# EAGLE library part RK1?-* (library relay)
1.5 GHz MICROWAVE RELAY NAiS Source: http://www.mew-europe.com/.. en_ds_61311_0000.pdf
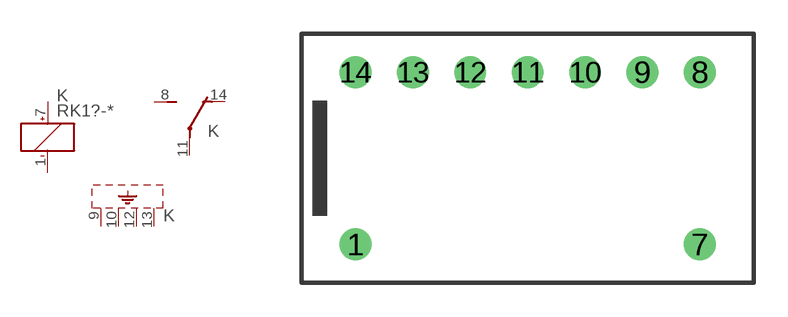
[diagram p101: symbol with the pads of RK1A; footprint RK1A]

Designator prefix K; gates 1=K+- 2=U S=SHIELD-4

## RK1-3V (OC_FARNELL: unknown; OC_NEWARK: unknown), RK1-4.5V (MPN: RK1-4.5V; OC_FARNELL: unknown; OC_NEWARK: 13P6878), RK1-5V (MPN: RK1-5V; OC_FARNELL: unknown; OC_NEWARK: 13P6879), RK1-6V (MF: AROMAT/ MATSUSHITA; MPN: RK1-6V; OC_FARNELL: unknown; OC_NEWARK: 10C9196), RK1-9V (OC_FARNELL: unknown; OC_NEWARK: unknown), RK1-12V (MPN: RK1-12V; OC_FARNELL: unknown; OC_NEWARK: 13P6876), RK1-24 (MPN: RK1-24V; OC_FARNELL: unknown; OC_NEWARK: 13P6877)  [RK1A]
1  1:-  pas
7  1:+  pas
8  2:S  pas
9  S:SH  pas
10  S:SH  pas
11  2:P  pas
12  S:SH  pas
13  S:SH  pas
14  2:O  pas

## RK1R-3V (OC_FARNELL: unknown; OC_NEWARK: unknown), RK1R-4.5V (OC_FARNELL: unknown; OC_NEWARK: unknown), RK1R-5V (OC_FARNELL: unknown; OC_NEWARK: unknown), RK1R-6V (OC_FARNELL: unknown; OC_NEWARK: unknown), RK1R-9V (OC_FARNELL: unknown; OC_NEWARK: unknown), RK1R-12V (OC_FARNELL: unknown; OC_NEWARK: unknown), RK1R-24V (OC_FARNELL: unknown; OC_NEWARK: unknown)  [RK1A]
1  1:-  pas
7  1:+  pas
8  2:O  pas
9  S:SH  pas
10  S:SH  pas
11  2:P  pas
12  S:SH  pas
13  S:SH  pas
14  2:S  pas

## RK1-L-3V (OC_FARNELL: unknown; OC_NEWARK: unknown), RK1-L-4.5V (MPN: RK1-L-4.5V; OC_FARNELL: unknown; OC_NEWARK: 11N5893), RK1-L-5V (MF: AROMAT/ MATSUSHITA; MPN: RK1-L-5V; OC_FARNELL: unknown; OC_NEWARK: 10C9186), RK1-L-6V (OC_FARNELL: unknown; OC_NEWARK: unknown), RK1-L-9V (OC_FARNELL: unknown; OC_NEWARK: unknown), RK1-L-12V (OC_FARNELL: unknown; OC_NEWARK: unknown), RK1-L-24V (OC_FARNELL: unknown; OC_NEWARK: unknown)  [RK1A]
1  1:+  pas
7  1:-  pas
8  2:S  pas
9  S:SH  pas
10  S:SH  pas
11  2:P  pas
12  S:SH  pas
13  S:SH  pas
14  2:O  pas

## RK1R-L-3V (OC_FARNELL: unknown; OC_NEWARK: unknown), RK1R-L-4.5V (OC_FARNELL: unknown; OC_NEWARK: unknown), RK1R-L-5V (OC_FARNELL: unknown; OC_NEWARK: unknown), RK1R-L-6V (OC_FARNELL: unknown; OC_NEWARK: unknown), RK1R-L-9V (OC_FARNELL: unknown; OC_NEWARK: unknown), RK1R-L-12V (OC_FARNELL: unknown; OC_NEWARK: unknown), RK1R-L-24V (OC_FARNELL: unknown; OC_NEWARK: unknown)  [RK1A]
1  1:+  pas
7  1:-  pas
8  2:O  pas
9  S:SH  pas
10  S:SH  pas
11  2:P  pas
12  S:SH  pas
13  S:SH  pas
14  2:S  pas

## Footprint RK1A (pad centres in mm)
1.5 GHz MICROWAVE RELAY NAiS Source: http://www.mew-europe.com/.. en_ds_61311_0000.pdf
drill 0.9 round: 1 -7.62,-3.81; 7 7.62,-3.81; 8 7.62,3.81; 9 5.08,3.81; 10 2.54,3.81; 11 0,3.81; 12 -2.54,3.81; 13 -5.08,3.81; 14 -7.62,3.81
